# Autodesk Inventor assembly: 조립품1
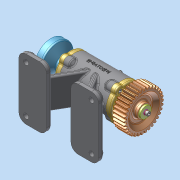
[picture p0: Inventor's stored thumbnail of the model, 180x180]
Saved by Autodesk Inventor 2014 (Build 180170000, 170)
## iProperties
Created: 2026-04
Part Number: 조립품1
Document SubType Name: Assembly
Designer: dg
Author: dg
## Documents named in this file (16)
- C:\Users\dg\Desktop\760403V1006\조립품1.iam
- C:\Users\dg\Desktop\760403V1006\부품2.ipt
- C:\Users\dg\Desktop\760403V1006\Imported Components\축\축.ipt
- C:\Users\dg\Desktop\760403V1006\Imported Components\평행 키 4x4x14\평행 키 4x4x14.ipt
- C:\Users\dg\Desktop\760403V1006\Imported Components\깊은 홈 볼 베어링 6004\깊은 홈 볼 베어링 6004.ipt
- C:\Users\dg\Desktop\760403V1006\Imported Components\커버\커버.ipt
- C:\Users\dg\Desktop\760403V1006\Imported Components\오일 실 20 35 8\오일 실 20 35 8.ipt
- C:\Users\dg\Desktop\760403V1006\Imported Components\6각 구멍붙이 볼트 M4x12\6각 구멍붙이 볼트 M4x12.ipt
- C:\Users\dg\Desktop\760403V1006\Imported Components\그리스 니플 M6x0,75\그리스 니플 M6x0,75.ipt
- C:\Users\dg\Desktop\760403V1006\Imported Components\실링\실링.ipt
- C:\Users\dg\Desktop\760403V1006\Imported Components\플러그 M6x0,75\플러그 M6x0,75.ipt
- C:\Users\dg\Desktop\760403V1006\Imported Components\플랜지\플랜지.ipt
- C:\Users\dg\Desktop\760403V1006\Imported Components\엔드 캡\엔드 캡.ipt
- C:\Users\dg\Desktop\760403V1006\Imported Components\평 와셔 M4\평 와셔 M4.ipt
- C:\Users\dg\Desktop\760403V1006\Imported Components\스프링 와셔 M4\스프링 와셔 M4.ipt
- C:\Users\dg\Desktop\760403V1006\Imported Components\스퍼 기어\스퍼 기어.ipt
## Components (11 placed, 4 different names)
1. 6각 구멍붙이 볼트 M4x12:1
2. 6각 구멍붙이 볼트 M4x12:2
3. 6각 구멍붙이 볼트 M4x12:3
4. 6각 구멍붙이 볼트 M4x12:4
5. 6각 구멍붙이 볼트 M4x12:5
6. 6각 구멍붙이 볼트 M4x12:6
7. 그리스 니플 M6x0,75:1
8. 플러그 M6x0,75:1
9. 플랜지:1
10. 6각 구멍붙이 볼트 M4x12:7
11. 6각 구멍붙이 볼트 M4x12:8
